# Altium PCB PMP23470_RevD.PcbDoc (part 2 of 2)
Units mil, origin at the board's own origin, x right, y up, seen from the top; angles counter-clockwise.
Board outline 2000 x 2300 mil, 2 copper layers (Top Layer, Bottom Layer), stack 61.2 mil thick; 73 components, 36 nets, 176 pads, 81 vias.
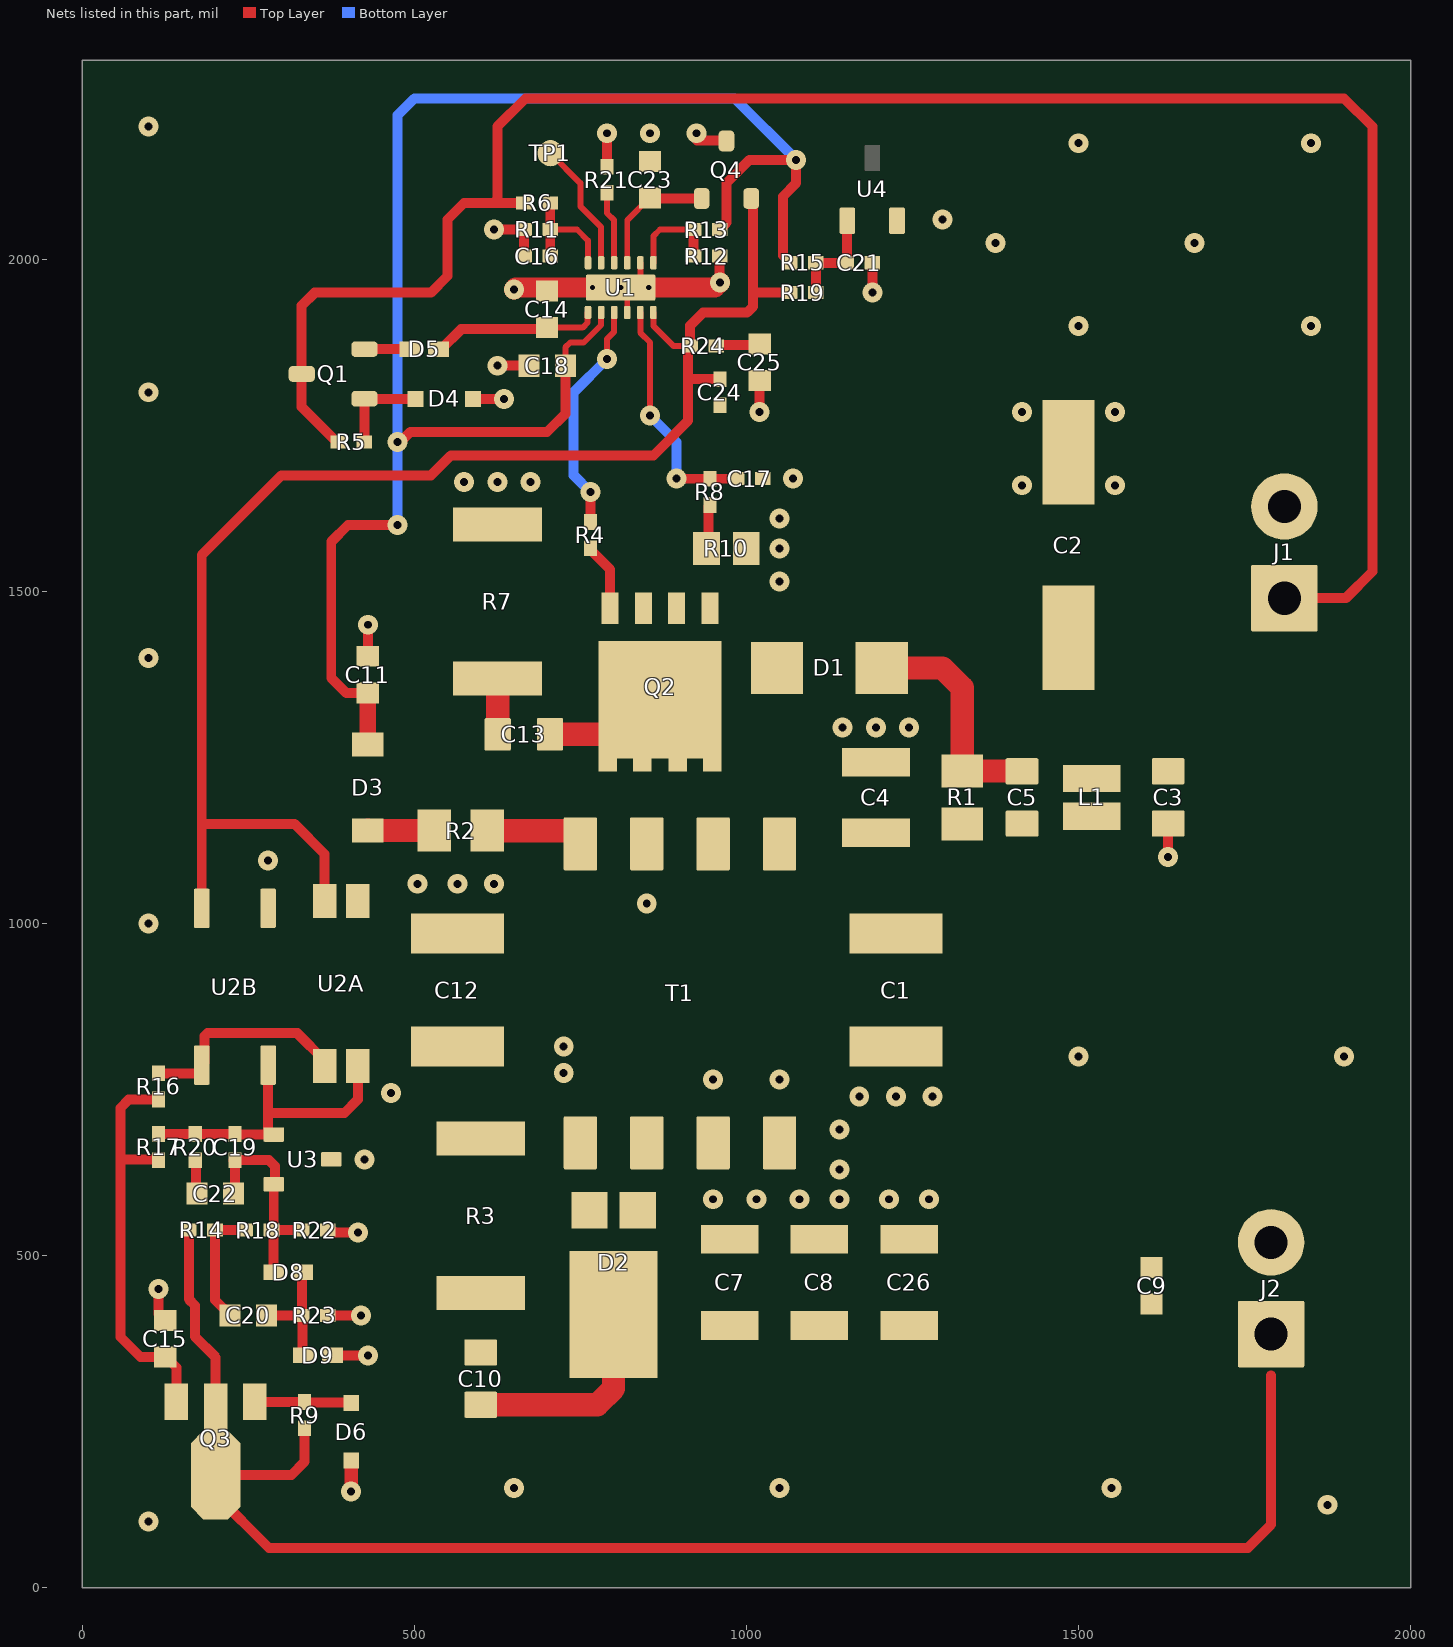
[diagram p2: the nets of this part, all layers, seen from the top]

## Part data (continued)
U2B: library part CMP-0098363-1, "3.75-kVRMS, Single-Channel Opto-Emulator with Transistor Output", Emiiter Collector Voltage=7V, Forward Current=10mA, Manufacturer="Texas Instruments", Operating Temperature Range="to +150°C", Power_TotalModule=200mW, Voltage_Isolation_Vrms=3750Vrms
U3: library part CMP-0084729-1, "Programmable Shunt Regulator with Optimized Reference Current, DBZ0003A (SOT-23-3)", Alternate Manufacturer="Texas Instruments"
U4: library part CMP-0033034-1, "Precision Micropower Shunt Voltage Reference, 1% accuracy, 5 V, 15 ppm / degC, 15 mA, -40 to 85 degC, 3-pin SOT-23 (DBZ), Green (RoHS & no Sb/Br)", Manufacturer="Texas Instruments", Rating=Catalog, Temp Coeff(Max)(ppm/ degree C)=150, Temp Coeff(Typ)(ppm/ degree C)=15

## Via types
v1: diameter 30, hole 12, Top Layer to Bottom Layer, 78 vias
v2: diameter 19.68, hole 7.87, Top Layer to Bottom Layer, 3 vias

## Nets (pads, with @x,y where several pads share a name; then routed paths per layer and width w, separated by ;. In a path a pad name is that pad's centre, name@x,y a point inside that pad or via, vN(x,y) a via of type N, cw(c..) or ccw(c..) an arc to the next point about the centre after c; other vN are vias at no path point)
GND: C1.1 C7.1 C8.1 C9.2 C12.1 C15.1 C26.1 D6.2 D9.2 J2.2 R22.2 R23.2 T1.5 T1.6 U3.3 | length 249.1
  Top Layer w15: v1(115,450) 115,412.56 115.77,411.79 115.77,410.81 124.02,402.56 C15.1@125,402.56 ; R23.2@369.69,410 v1(420,410) ; R22.2@369.88,538.47 372.22,536.13 378.88,536.13 380.01,535 v1(415,535) ; D9.2@376.65,350 v1(430,350)
  Top Layer w20: v1(405,145) D6.2@405,191.69
  other v1: 100,100 1875,125 650,150 1050,150 1550,150 950,585 1015,585 1080,585 1140,585 1215,585 1275,585 1140,630 425,645 1140,690 1170,740 1225,740 1280,740 465,745 950,765 1050,765 725,775 1500,800 1900,800 725,815
NetC1_2: C1.2 C4.2 C5.2 L1.2 R1.1 T1.4
NetC2_1: C2.1 C3.2 J1.1 L1.1 Q1.3 R5.1 R6.1 | length 2966.7
  Top Layer w15: R5.1@385.32,1725 383.35,1725 330.51,1777.83 Q1.3@330.51,1827.6 330.51,1930.51 350,1950 525,1950 550,1975 550,2060 575,2085 620.16,2085 ; R6.1@665.32,2085 620.16,2085 ; J1.1@1810,1490 1902.5,1490 1942.5,1530 1942.5,2200 1900,2242.5 667.5,2242.5 625,2200 625,2089.84 620.16,2085
NetC5_1: C5.1 D1.1 R1.2 | length 348.9
  Top Layer w35: D1.1@1203.74,1385 1295,1385 1325,1355 R1.2@1325,1230 1325.32,1229.69 1414.68,1229.69 C5.1@1415,1229.37
NetC7_2: C7.2 C8.2 C9.1 C10.2 C26.2 D2.3 J2.1 Q3.2 Q3.4 R9.2 R14.1 | length 2791.2
  Top Layer w15: R14.1@160.51,538.47 160.51,434.49 170,425 170,378 200.94,347.06 Q3.2@200.94,272.13 Q3.4@200.94,169.76 ; R9.2@335,240.31 335,190 315,170 201.18,170 Q3.4@200.94,169.76 ; 1790,320 1790,95 1755,60 281.18,60 200.94,140.24 Q3.4@200.94,169.76
  Top Layer w35: C10.2@600,275.63 775.63,275.63 800,300 D2.3@800,411.61
NetC10_1: C10.1 R3.2
NetC13_1: C13.1 R7.1 | length 84.1
  Top Layer w35: R7.1@625,1368.86 625.63,1368.23 C13.1@625.63,1285
NetC13_2: C13.2 D1.2 Q2.5 Q2.6 Q2.7 Q2.8 Q2.9 T1.3 | length 187.3
  Top Layer w35: C13.2@704.37,1285 817.8,1285 Q2.9@870,1337.2
NetC14_2: C14.2 D5.1 U1.1 | length 256.4
  Top Layer w9: C14.2@700,1897.44 753.58,1897.44 761.15,1905.02 761.15,1919.78 U1.1@761.57,1920.2
  Top Layer w15: D5.1@536.65,1865 540.59,1865 570.59,1895 697.56,1895 C14.2@700,1897.44
NetC15_2: C15.2 Q3.3 R16.1 R17.1 | length 621
  Top Layer w15: R16.1@115,735.32 114.68,735 70,735 57.5,722.5 57.5,645 ; R17.1@115.2,643.79 113.99,645 57.5,645 ; Q3.3@141.89,280 141.89,331.54 125.98,347.44 C15.2@125,347.44 87.56,347.44 57.5,377.5 57.5,645
NetC16_2: C16.2 R6.2 R11.1 U1.12 | length 177.2
  Top Layer w9: R11.1@704.68,2045 745,2045 761.57,2028.43 U1.12@761.57,1995
  Top Layer w15: C16.2@704.69,2005 R11.1@704.68,2045 R6.2@704.69,2085
NetC17_2: C17.2 R8.2 U1.5 | length 363.4
  Top Layer w9: U1.5@840.32,1920.2 840.32,1889.68 855,1875 v1(855,1765)
  Top Layer w15: v1(895,1670) 895.16,1669.84 944.84,1669.84 R8.2@945,1669.69 945.16,1669.84 985.16,1669.84 C17.2@985.31,1670
  Bottom Layer w15: v1(855,1765) 895,1725 v1(895,1670)
NetC19_1: C19.1 C22.1 D8.1 R18.2 R22.1 U3.2 | length 319.8
  Top Layer w15: C22.1@227.75,593.47 C22.1@227.85,593.38 ; C22.1@230.04,595.76 C19.1@230.04,643.63 ; C19.1@230.2,643.79 281.21,643.79 290,635 290,609.21 U3.2@288.39,607.6 288.39,540.82 R18.2@286.04,538.47 ; R18.2@284.88,538.47 R18.2@286.04,538.47 ; D8.1@288.35,475 R18.2@288.35,536.13 ; R22.1@330.51,538.47 R18.2@286.04,538.47
  Top Layer w20: C22.1@227.75,593.47 C22.1@230.04,595.76 ; C19.1@230.04,643.63 C19.1@230.2,643.79
NetC19_2: C19.2 R17.2 R20.1 U2A.2 U2B.2 U3.1 | length 473.2
  Top Layer w15: R17.2@115.2,683.16 R20.1@170.2,683.16 C19.2@230.2,683.16 230.58,682.78 U3.1@283.09,682.78 ; U2B.2@280,786.89 280,715 ; U3.1@288.39,682.4 288.01,682.78 U3.1@283.09,682.78 ; U2A.2@415,785.98 415,735 395,715 280,715 ; 280,715 280,685.87 U3.1@283.09,682.78
NetC20_1: C20.1 D8.2 D9.1 R23.1 | length 180
  Top Layer w15: C20.1@277.56,410 R23.1@330.32,410 R23.1@330.98,410.67 ; D8.2@331.65,475 330.98,474.33 R23.1@330.98,410.67 ; D9.1@333.35,350 331.83,351.52 331.83,409.82 R23.1@330.98,410.67
NetC20_2: C20.2 R14.2 R18.1 | length 183.4
  Top Layer w15: C20.2@222.44,410 222.44,410.98 199.88,433.54 R14.2@199.88,538.47 R18.1@245.51,538.47
NetC21_1: C21.1 R15.2 R19.1 U4.1 | length 156
  Top Layer w15: R19.1@1104.68,1950 R15.2@1104.69,1995 ; R15.2@1105.69,1996 R15.2@1104.69,1995 ; U4.1@1152.05,2058.25 1151.18,2057.39 1151.18,1995.87 C21.1@1150.32,1995 R15.2@1104.69,1995
NetC22_2: C22.2 R20.2 | length 51.3
  Top Layer w15: R20.2@170.2,643.79 171.42,642.57 171.42,594.7 C22.2@172.64,593.47
NetC23_1: C23.1 Q4.1 U1.9 | length 190.2
  Top Layer w9: U1.9@820.63,1995 820.63,2059.05 854.02,2092.44 C23.1@855,2092.44
  Top Layer w15: C23.1@855,2092.44 855.37,2092.07 932.22,2092.07 Q4.1@932.6,2091.69
NetC24_1: C24.1 Q4.2 R19.2 R24.1 U1.6 U2A.4 U2B.4 | length 2228.1
  Top Layer w9: U1.6@860,1920.2 860,1900 890,1870 R24.1@914.78,1870
  Top Layer w15: U2B.4@180,1023.11 180,1150 ; U2A.4@365,1034.02 365,1105 320,1150 180,1150 ; C24.1@960,1819.68 912.76,1819.68 912.44,1820 ; Q4.2@1007.4,2091.69 1010,2089.09 1010,1950 ; R19.2@1065.31,1950 1010,1950 ; 180,1150 180,1555 300,1675 525,1675 555,1705 860,1705 912.44,1757.44 912.44,1820 ; 912.44,1820 912.44,1867.66 914.78,1870 R24.1@915.32,1870 915.32,1900.32 935,1920 1001.21,1920 1010,1928.79 1010,1950
NetC25_2: C25.2 R24.2 | length 66.4
  Top Layer w15: R24.2@954.69,1870 955.96,1871.28 1018.72,1871.28 C25.2@1020,1872.56
NetD2_1: D2.1 D2.2 R3.1 T1.7 T1.8
NetD3_2: D3.2 R2.1 | length 100.2
  Top Layer w35: D3.2@430,1140.53 430.27,1140.27 529.73,1140.27 R2.1@530,1140
NetD4_1: D4.1 Q1.1 R5.2 | length 141.9
  Top Layer w15: R5.2@424.69,1725 424.84,1725.16 424.84,1789.84 425.1,1790.1 501.59,1790.1 D4.1@501.69,1790
NetD5_2: D5.2 Q1.2 | length 68.3
  Top Layer w15: Q1.2@425,1865 D5.2@493.35,1865
NetD6_1: D6.1 Q3.1 R9.1 | length 145.7
  Top Layer w15: Q3.1@260,280 260.32,279.68 R9.1@335,279.68 335.69,279 404.31,279 D6.1@405,278.31
NetQ2_1: Q2.1 Q2.2 Q2.3 R8.1 R10.1 | length 67.4
  Top Layer w15: R10.1@940.08,1565 942.66,1567.58 942.66,1627.97 R8.1@945,1630.32
NetQ2_4: Q2.4 R4.1 | length 102.7
  Top Layer w15: R4.1@765,1565.32 765,1563.35 795,1533.35 Q2.4@795,1475
NetR2_2: R2.2 T1.1 | length 152
  Top Layer w35: R2.2@610,1140 742.5,1140 750,1132.5 T1.1@750,1123.62
NetR4_2: R4.2 U1.3 | length 352.9
  Top Layer w9: v1(790,1850) 790,1880 800.94,1890.94 U1.3@800.94,1920.2
  Top Layer w15: R4.2@765,1604.69 v1(765,1650) ; v1@790,1848.22 v1(790,1850)
  Bottom Layer w15: v1(765,1650) 740,1675 740,1800 v1(790,1850)
NetR12_2: R12.2 R13.2 U1.7 | length 144.5
  Top Layer w9: U1.7@860,1995 860,2035 870,2045 R13.2@920.31,2045
  Top Layer w15: R12.2@920.31,2005 R13.2@920.31,2045
NetR16_2: R16.2 U2A.1 U2B.1 | length 327.6
  Top Layer w15: R16.2@115,774.69 175.69,774.69 180,779 U2B.1@180,786.89 184.31,791.2 184.31,830.52 188.79,835 323.86,835 365,793.86 U2A.1@365,785.98
NetR21_1: R21.1 U1.10 | length 109.8
  Top Layer w9: R21.1@790,2100.32 790,2070 800.94,2059.06 U1.10@800.94,1995
NetTP1_1: TP1.1 U1.11 | length 196.6
  Top Layer w9: TP1.1@705,2160 750,2115 750,2080 781.26,2048.74 U1.11@781.26,1995
PGND: C2.2 C3.1 C4.1 C11.1 C12.2 C14.1 C16.1 C17.1 C18.1 C21.2 C23.2 C24.2 C25.1 D4.2 J1.2 Q4.3 R7.2 R10.2 R11.2 R12.1 R21.2 T1.2 U1.4 U1.8 U1.13 U2A.3 U2B.3 U4.2 | length 814.9
  Top Layer w9: v2(810.79,1957.6) 820.63,1947.76 U1.4@820.63,1920.2 ; U1.8@840.32,1995 840.32,1970.39 v2(853.11,1957.6)
  Top Layer w15: C11.1@430,1402.56 v1(430,1450) ; D4.2@588.31,1790 v1(635,1790) ; v1(620,2045) R11.2@665.31,2045 C16.1@665.32,2005 ; v1(625,1840) C18.1@672.44,1840 ; R21.2@790,2139.69 v1@790,2185 ; v1@925,2180 925.85,2179.15 969.15,2179.15 Q4.3@970,2178.31 ; R12.1@959.68,2005 959.84,2004.84 959.84,1965.16 v1(960,1965) ; v1(1020,1770) C25.1@1020,1817.44 ; C21.2@1189.69,1995 1189.84,1994.84 1189.84,1950.16 v1(1190,1950) ; v1(1635,1100) C3.1@1635,1150.63
  Top Layer w30: v1(650,1955) 652.6,1957.6 v2(768.46,1957.6) ; v2(853.11,1957.6) 952.6,1957.6 v1(960,1965)
  other v1: 100,1000 850,1030 505,1060 565,1060 620,1060 280,1095 1145,1295 1195,1295 1245,1295 100,1400 1050,1515 1050,1565 1050,1610 1415,1660 1555,1660 575,1665 625,1665 675,1665 1070,1670 1415,1770 1555,1770 100,1800 1500,1900 1850,1900 1375,2025 1675,2025 1295,2060 1500,2175 1850,2175 790,2190 855,2190 925,2190 100,2200
VCC: C11.2 C18.2 D3.1 R13.1 R15.1 U1.2 | length 2544.8
  Top Layer w9: C18.2@727.56,1840 727.56,1867.56 735,1875 755,1875 781.26,1901.26 U1.2@781.26,1920.2
  Top Layer w15: C11.2@430,1347.44 397.56,1347.44 375,1370 375,1575 400,1600 v1(475,1600) ; v1(475,1725) 479.06,1725 494.5,1740.44 574.56,1740.44 575,1740 700,1740 727.56,1767.56 C18.2@727.56,1840 ; R13.1@959.68,2045 961.65,2045 964,2047.34 964,2049.31 970,2055.32 970,2115.32 1004.68,2150 v1(1075,2150) 1075,2115 1055,2095 1055,2006.13 1061,2000.13 1061,1997.34 1063.35,1995 R15.1@1065.32,1995
  Top Layer w25: D3.1@430,1269.47 C11.2@430,1347.44
  Bottom Layer w15: v1(475,1600) v1(475,1725) 475,2217.5 500,2242.5 982.5,2242.5 v1(1075,2150)
pads on no net: U4.3

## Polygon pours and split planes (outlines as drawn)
NetC7_2 on Top Layer "TOP_LAYER_NETC7_2_P022" (solid, remove dead copper, pour order 22): 1635,195 1950,195 1950,440 1550,440 890,440 890,510 730,510 730,195
PGND on Top Layer "TOP_LAYER_PGND_P024" (solid, remove dead copper, pour order 24): 50,2250 1950,2250 1950,955 50,955
GND on Top Layer "TOP_LAYER_GND_P023" (solid, remove dead copper, pour order 23): 1950,845 1950,50 50,50 50,845
NetQ2_1 on Top Layer "TOP_LAYER_NETQ2_1_P019" (solid, remove dead copper, pour order 19): 960,1450 830,1450 830,1595 960,1595
NetC2_1 on Top Layer "TOP_LAYER_NETC2_1_P018" (solid, remove dead copper, pour order 18): 1470,1200 1470,1300 1400,1300 1400,1545 1950,1545 1950,1200
NetC1_2 on Top Layer "TOP_LAYER_NETC1_2_P017" (solid, remove dead copper, pour order 17): 1020,1180 1570,1180 1570,955 1020,955
NetC13_2 on Top Layer "TOP_LAYER_NETC13_2_P016" (solid, remove dead copper, pour order 16): 910.8,1070.25 910,1071.05 910,1210 750,1210 750,1425 1090,1425 1090,1210 990,1210 990,1070
NetC10_1 on Top Layer "TOP_LAYER_NETC10_1_P015" (solid, remove dead copper, pour order 15): 675,330 675,510 520,510 520,330
NetD2_1 on Top Layer "TOP_LAYER_NETD2_1_P014" (solid, remove dead copper, pour order 14): 880,540 520,540 520,730 880,730
GND on Bottom Layer "BOTTOM_LAYER_GND_P020" (solid, remove dead copper, pour order 20): 1950,845 50,845 50,50 1950,50
PGND on Bottom Layer "BOTTOM_LAYER_PGND_P021" (solid, remove dead copper, pour order 21): 50,2250 1950,2250 1950,955 50,955

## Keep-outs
Keep-Out Layer:
  text ".Layer_Name" at 577,-858.49 h60

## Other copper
Top Layer:
  rectangle net NetC7_2: 180,215 225,245
  text ".Layer_Name" at 577,-858.49 h60
Bottom Layer:
  text ".Layer_Name" at 577,-858.49 h60

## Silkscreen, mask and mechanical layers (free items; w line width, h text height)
Top Overlay:
  lines w10: 494.51,730 495,730 525,760
  text "PGND" at 1944,1766 h35 r90
  text "VIN" at 1939,1261 h35 r90
  text "'.PRJ_Number'.PCB_Rev-" at 210,1200 h108.27 r90
  text "GND" at 1939,646 h35 r90
  text "VOUT" at 1944,121 h35 r90
  text ".Layer_Name" at 577,-858.49 h60
Bottom Overlay:
  text ".Layer_Name" at 577,-858.49 h60
Top Paste:
  text ".Layer_Name" at 577,-858.49 h60
Bottom Paste:
  text ".Layer_Name" at 577,-858.49 h60
Top Solder:
  text ".Layer_Name" at 577,-858.49 h60
  text ".Layer_Name" at 577,-858.49 h60
Bottom Solder:
  text ".Layer_Name" at 577,-858.49 h60
Drill Guide:
  text ".Layer_Name" at 577,-858.49 h60
M1 Board Outline:
  the board outline again, w10
  text ".Layer_Name" at 577,-858.49 h60
M2 Board Dimensions:
  rectangle: 0,-275 125,-150
  rectangle: 125,-400 500,-275
  lines w7: 0,-275 1000,-275 ; 125,-400 125,-150 ; 250,-400 250,-150 ; 500,-400 500,-150 ; 750,-400 750,-150 ; 0,-400 1000,-400 1000,-150 0,-150 0,-400
  text ".Layer_Name" at 577,-858.49 h60
M3 3D STEP Top:
  text ".Layer_Name" at 577,-858.49 h60
M4 3D STEP Bottom:
  text ".Layer_Name" at 577,-858.49 h60
M5 Assembly Top:
  lines w10: -292,-930.17 6308,-930.17 ; -292,-726.83 6310,-726.83 ; -292,-523.5 -292,-1133.5 3713,-1133.5 6310,-1133.5 6310,-523.5 -291.5,-523.5 -291.5,-1133.5 1284,-1133.5 ; 2173,-1133.5 2173,-523.5 ; 3440,-726.83 3440,-523.5 ; 4280,-726.83 4280,-523.5 ; 4902,-1140 4902,-937.17
  text "COMPONENTS MARKED 'DNP' SHOULD NOT BE POPULATED." at 1153.5,-318.5 h60
  text "ASSEMBLY VARIANT:" at 1153,-434 h60
  text ".VariantName" at 2189,-434 h60
  text "PCB VIEWED FROM TOP SIDE" at -228.5,-655.67 h60
  text "BOARD #:" at 2248,-655.67 h60
  text ".PRJ_Number" at 2793.5,-655.67 h60
  text "REV:" at 3638,-655.67 h60
  text ".PCB_Rev" at 3929.5,-655.67 h60
  text "SVN REV:" at 4476,-655.67 h60
  text ".VersionControl_RevNumber" at 4982,-655.67 h60
  text "TID #:" at 2248,-859 h60
  text ".TID" at 2793.5,-859 h60
  text "PLOT NAME =" at -228.5,-1064.34 h60
  text ".plot_File_Name" at 577,-1064.34 h60
  text "GENERATED    :" at 2250,-1064.34 h60
  text ".Print_Date" at 3119.5,-1064.34 h60
  text ".Print_Time" at 3848.5,-1064.34 h60
  text "TEXAS INSTRUMENTS" at 5113,-1064.34 h60
M6 Assembly Bottom:
  lines w10: -292.5,-727.33 6309.5,-727.33 ; -290.5,-930.67 6309.5,-930.67 ; 1115.5,-1140.5 1115.5,-937.67 ; 1737.5,-727.33 1737.5,-524 ; 2577.5,-727.33 2577.5,-524 ; 3844.5,-1134 3844.5,-524 ; 4733.5,-1134 6309,-1134 6309,-524 -292.5,-524 -292.5,-1134 2304.5,-1134 6309.5,-1134 6309.5,-524
  text "COMPONENTS MARKED 'DNP' SHOULD NOT BE POPULATED." at 6102,-318 h60
  text ".VariantName" at 5058,-434 h60
  text "ASSEMBLY VARIANT:" at 6097,-434 h60
  text ".VersionControl_RevNumber" at 1035.5,-656.17 h60
  text "SVN REV:" at 1541.5,-656.17 h60
  text ".PCB_Rev" at 2088,-656.17 h60
  text "REV:" at 2379.5,-656.17 h60
  text ".PRJ_Number" at 3224,-656.17 h60
  text "BOARD #:" at 3769.5,-656.17 h60
  text "PCB VIEWED FROM BOTTOM SIDE" at 6246,-656.17 h60
  text ".TID" at 3224,-859.5 h60
  text "TID #:" at 3769.5,-859.5 h60
  text "TEXAS INSTRUMENTS" at 904.5,-1064.84 h60
  text ".Print_Time" at 2169,-1064.84 h60
  text ".Print_Date" at 2898,-1064.84 h60
  text "GENERATED    :" at 3767.5,-1064.84 h60
  text ".plot_File_Name" at 5440.5,-1064.84 h60
  text "PLOT NAME =" at 6246,-1064.84 h60
M9 Title Sheet:
  drawing of 57 lines, arcs and shapes, not listed
  text "1" at 739.84,8036.5 h70
  text "2" at 3235.5,8036.5 h70
  text "3" at 5724.84,8036.5 h70
  text "4" at 8231.51,8036.5 h70
  text "5" at 10730.5,8036.5 h70
  text "6" at 13235.5,8036.5 h70
  text "A" at -416.5,6893.5 h70
  text "A" at 14383.5,6893.5 h70
  text "B" at -416.5,4513.5 h70
  text "B" at 14383.5,4513.5 h70
  text "C" at -416.5,2138.5 h70
  text "C" at 14383.5,2138.5 h70
  text "PROJECT TITLE:" at 11343.5,277.5 h45
  text ".PRJ_Title" at 11393.5,144.17 h70
  text "DESIGNED FOR:" at 11343.5,-23.5 h45
  text ".PRJ_Customer" at 11393.5,-163.5 h70
  text "D" at -416.5,-231.5 h70
  text "D" at 14383.5,-231.5 h70
  text "FILE NAME:" at 11343.5,-323.5 h45
  text ".PCB_File_Name_No_Path" at 11393.5,-443.5 h70
  text "Texas Instruments (TI) and/or its licensors do not warrant the accuracy or completeness of this specification" at 6374,-605.34 h45
  text "ENGINEER:" at 11343.5,-613.5 h45
  text "LAYOUT BY:" at 12848.5,-613.5 h45
  text "or any information contained therein. TI and/or its licensors do not warrant that this design will meet" at 6329.01,-718 h45
  text ".PRJ_Engineer" at 11393.5,-768.49 h70
  text ".PCB_Layout" at 12899,-768.49 h70
  text "the specifications, will be suitable for your application or fit for any particular purpose, or will operate in" at 6329.01,-830.67 h45
  text ".Layer_Name" at 577,-858.49 h60
  text "ALTIUM DESIGNER VERSION:" at 12848.5,-923.5 h45
  text "an implementation. TI and/or its licensors do not warrant that the design is production worthy. You should" at 6329.01,-943.33 h45
  text "completely validate and test your design implementation to confirm the system functionality for your application." at 6374,-1056 h45
  text ".print_Scale" at 11393.5,-1056.83 h70
  text ".Application_BuildNumber" at 12899,-1056.83 h70
  text "1" at 739.84,-1263.5 h70
  text "2" at 3235.5,-1263.5 h70
  text "3" at 5724.84,-1263.5 h70
  text "4" at 8231.51,-1263.5 h70
  text "5" at 10730.5,-1263.5 h70
  text "6" at 13235.5,-1263.5 h70
M10 Fab Notes:
  drawing of 189 lines, arcs and shapes, not listed
  text "DESIGN INFORMATION" at 12382.02,6356.17 h60
  text "MIN. TRACK WIDTH:" at 11737.46,6224.05 h60
  text "8" at 12833.7,6224.05 h60
  text "MIL" at 12988.46,6224.05 h60
  text "MIN. CLEARANCE:" at 11737.46,6099.92 h60
  text "0.2" at 12773.7,6099.93 h60
  text "mm" at 12988.46,6099.92 h60
  text "MIN. VIA PAD SIZE:" at 11737.46,5975.8 h60
  text "24" at 12803.71,5975.8 h60
  text "MIL" at 12988.46,5975.8 h60
  text "0.05mm (2MIL)" at 12432.46,5845.9 h60
  text "MINIMUM ANNULAR RING" at 11408.23,5837.67 h60
  text "EXTERNAL" at 13140.46,5837.67 h60
  text "PER" at 11608.23,5727.55 h60
  text "IPC-D-275 CLASS 2 LEVEL C" at 11828.23,5727.54 h60
  text "MIL, HOLES" at 13316.46,5627.07 h60
  text "+/-" at 12924,5618.48 h60
  text "+/-" at 13778,5618.48 h60
  text "REGISTRATION TOLERANCES:" at 11408.23,5617.42 h60
  text "METAL" at 12608,5617.42 h60
  text "5" at 13184.2,5617.42 h60
  text "3" at 14017.2,5617.42 h60
  text "MIL" at 14133.46,5617.42 h60
  text "HOLE SIZE TOLERANCE (UNLESS OTHERWISE SPECIFIED):" at 11408.23,5519.1 h60
  text "+/-" at 13778,5516.23 h60
  text "3" at 14017.2,5515.17 h60
  text "MIL" at 14133.46,5515.17 h60
  text "MATERIAL:" at 11333.46,5377.52 h60
  text "FR-4 High Tg" at 12319.9,5249 h60
  text "X" at 12175.46,5241.01 h60
  text "FR-408" at 11754.46,5236.49 h60
  text "OTHER" at 13242.46,5236.49 h60
  text "62 MIL (1.6mm) +/-10%" at 12074.56,5093.46 h60
  text "X" at 11954.46,5091.01 h60
  text "THICKNESS:" at 11408.23,5085.24 h60
  text "OTHER" at 13359.46,5085.24 h60
  text "TOLERANCE:" at 11408.23,4946.92 h60
  text "X" at 12256.46,4946.92 h60
  text "ANSI IPC-6012 TYPE 3 CLASS 2" at 12434.48,4946.92 h60
  text "OTHER +/-" at 12434.46,4802.73 h60
  text "BOW & TWIST:" at 11408.23,4657.54 h60
  text "X" at 12256.46,4657.54 h60
  text "ANSI IPC-6012 TYPE 3 CLASS 2" at 12434.48,4657.54 h60
  text "OTHER +/-" at 12434.46,4510.85 h60
  text "DRILLING:" at 11333.46,4380.23 h60
  text "NC_DRILL FILES" at 13094.46,4275.04 h60
  text "REFERENCE:" at 11408.23,4271.1 h60
  text "X" at 12065.46,4271.01 h60
  text "AS SHOWN" at 12243.46,4271.1 h60
  text "X" at 12966.46,4271.1 h60
  text "OTHER" at 13392.46,4128.85 h60
  text "PTH COPPER THICKNESS:" at 11407.91,4125.32 h60
  text "X" at 12547.14,4125.32 h60
  text "20-30 um" at 12675.14,4125.32 h60
  text "BOARD FINISH:" at 11333.46,3977.73 h60
  text "SILKSCREEN:" at 11488.68,3867.6 h60
  text "X" at 12446.46,3867.6 h60
  text "TOP" at 12563.46,3867.6 h60
  text "X" at 12956.46,3867.6 h60
  text "BOTTOM" at 13074.46,3867.6 h60
  text "SILKSCREEN COLOR:" at 11488.68,3712.41 h60
  text "X" at 12445.46,3712.41 h60
  text "WHITE" at 12563.46,3712.41 h60
  text "OTHER" at 13074.46,3712.41 h60
  text "X" at 12576.46,3568.96 h60
  text "GREEN" at 12694.46,3568.96 h60
  text "OTHER" at 13312.46,3568.96 h60
  text "SOLDER RESIST COLOR:" at 11488.68,3562.1 h60
  text "X" at 12576.46,3414.71 h60
  text "MATTE" at 12694.46,3414.71 h60
  text "SEMI-GLOSS" at 13312,3414.07 h60
  text "IMMERSION GOLD (ENIG)" at 12394.46,3241.94 h60
  text "ENEPIG" at 13732,3234.72 h60
  text "SURFACE FINISH:" at 11333.46,3233.72 h60
  text "X" at 12216.46,3233.72 h60
  text "IMM. TIN/SILVER OR EQUIV" at 11663,3096.4 h60
  text "OTHER" at 13094.46,3092.47 h60
  text "ARRAY/PANEL:" at 11333.46,2937.09 h60
  text "X" at 12215,2930 h60
  text "CUT AND TRIM PER M1 BOARD OUTLINE" at 12394.46,2928.87 h60
  text "N.C. ROUTE" at 12394.46,2792.9 h60
  text "V. SCORE" at 13260.46,2792.9 h60
  text "CERTIFICATION:" at 11333.46,2663.77 h60
  text "MATERIALS AND WORKMANSHIP FOR ALL PCBS" at 12058.46,2663.77 h60
  text "TO MEET OR EXCEED THE REQUIREMENTS OF:" at 12058.46,2569.71 h60
  text "X" at 11695.97,2441.08 h60
  text "ANSI IPC-A-600F CLASS ->" at 11823.96,2441.08 h60
  text "X" at 13471.97,2441.08 h60
  text "2" at 13581.96,2441.08 h60
  text "1" at 13266.96,2439.58 h60
  text "3" at 13935.96,2439.58 h60
  text "X" at 12507.97,2293.39 h60
  text "RoHS" at 12635.96,2293.39 h60
  text "OTHER" at 13280.36,2293.39 h60
  text "PER ORDER" at 13677.42,2293.39 h60
  text "ALL BOARDS MUST MEET OR EXCEED UL94-V0 REQUIREMENTS." at 11361,2139.57 h60
  text "PCB MUST BEAR THE UL94V-0 UL REGISTERED MATERIAL ID NUMBER" at 11361,2023.5 h60
  text "ADDITIONAL REQUIREMENTS:" at 11333.46,1854.08 h60
  text "MICROSECTION:" at 11408.23,1746.95 h60
  text "YES" at 12313.96,1746.95 h60
  text "REQUIRED" at 13175.46,1602.62 h60
  text "BARE BOARD ELEC. TEST:" at 11408.23,1599.76 h60
  text "NONE" at 12713.96,1599.76 h60
  text "X" at 13057.46,1599.76 h60
  text "PER ORDER" at 13767.46,1599.76 h60
  text "XX MIL VIAS REQUIRE NON-CONDUCTIVE FILL AND PLANARIZE" at 11576.38,1394.82 h59
  text "XX MIL VIAS REQUIRE CONDUCTIVE FILL AND PLANARIZE" at 11584.38,1290.84 h60
  text "OUTER XX MIL VIAS REQUIRE 50 OHM SINGLE-ENDED IMPEDANCE" at 11583.39,1127.46 h58
  text "LAYER 2 & 3 (INNER LAYERS) XX MIL WIDE, XX MIL SPACE / TRACES REQUIRE 100 OHM DIFFERENTIAL IMPEDANCE" at 11575.39,891.74 h60
  text ".Layer_Name" at 577,-858.49 h60
M11 Gerber Information:
  lines w10: -292,-930.17 6308,-930.17 ; -292,-726.83 6310,-726.83 ; -292,-523.5 -292,-1133.5 3713,-1133.5 6310,-1133.5 6310,-523.5 -291.5,-523.5 -291.5,-1133.5 1284,-1133.5 ; 2173,-1133.5 2173,-523.5 ; 3440,-726.83 3440,-523.5 ; 4280,-726.83 4280,-523.5 ; 4902,-1140 4902,-937.17
  text "ALL ARTWORK VIEWED FROM TOP SIDE" at -228.5,-655.67 h60
  text "BOARD #:" at 2248,-655.67 h60
  text ".PRJ_Number" at 2793.5,-655.67 h60
  text "REV:" at 3638,-655.67 h60
  text ".PCB_Rev" at 3929.5,-655.67 h60
  text "SVN REV:" at 4476,-655.67 h60
  text ".VersionControl_RevNumber" at 4982,-655.67 h60
  text "LAYER NAME =" at -228.5,-858.49 h60
  text "TID #:" at 2248,-859 h60
  text ".TID" at 2793.5,-859 h60
  text "PLOT NAME =" at -228.5,-1064.34 h60
  text ".plot_File_Name" at 577,-1064.34 h60
  text "GENERATED    :" at 2250,-1064.34 h60
  text ".Print_Date" at 3119.5,-1064.34 h60
  text ".Print_Time" at 3848.5,-1064.34 h60
  text "TEXAS INSTRUMENTS" at 5113,-1064.34 h60
M12 Stackup:
  drawing of 191 lines, arcs and shapes, not listed
  text "Layer" at 9771.2,7790 h60
  text "Name" at 10181.11,7790 h60
  text "Material" at 11110.85,7790 h60
  text "Thickness" at 11970.62,7790 h60
  text "Constant" at 12620.46,7790 h60
  text "Board Layer Stack" at 13190.32,7790 h60
  text "Top Overlay" at 10181.11,7670 h60
  text "Top Solder" at 10181.11,7550 h60
  text "Solder Resist" at 11110.85,7550 h60
  text "0.40mil" at 11970.62,7550 h60
  text "3.5" at 12620.46,7550 h60
  text "1" at 9771.2,7430 h60
  text "Top Layer" at 10181.11,7430 h60
  text "2.80mil" at 11970.62,7430 h60
  text "Dielectric1" at 10181.11,7310 h60
  text "FR-4" at 11110.85,7310 h60
  text "55.60mil" at 11970.62,7310 h60
  text "4.8" at 12620.46,7310 h60
  text "2" at 9771.2,7190 h60
  text "Bottom Layer" at 10181.11,7190 h60
  text "2.80mil" at 11970.62,7190 h60
  text "Bottom Solder" at 10181.11,7070 h60
  text "Solder Resist" at 11110.85,7070 h60
  text "0.40mil" at 11970.62,7070 h60
  text "3.5" at 12620.46,7070 h60
  text "Bottom Overlay" at 10181.11,6950 h60
  text ".Layer_Name" at 577,-858.49 h60
M13 Component Bodies Top:
  text ".Layer_Name" at 577,-858.49 h60
M14 Component Bodies Bottom:
  text ".Layer_Name" at 577,-858.49 h60
M15 Courtyards Top:
  text ".Layer_Name" at 577,-858.49 h60
M16 Courtyards Bottom:
  text ".Layer_Name" at 577,-858.49 h60
Drill Drawing:
  text ".Layer_Name" at 577,-858.49 h60
M17 Embedded Cavity:
  text ".Layer_Name" at 577,-858.49 h60
M18 Embedded Assembly:
  text ".Layer_Name" at 577,-858.49 h60
M19 Embedded Keepout:
  text ".Layer_Name" at 577,-858.49 h60

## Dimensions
0,-400 to 1000,-400 on M2 Board Dimensions
0,0 to 0,2300 on M2 Board Dimensions
0,0 to 2000,0 on M2 Board Dimensions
